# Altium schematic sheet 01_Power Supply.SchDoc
size 264 x 185 mm
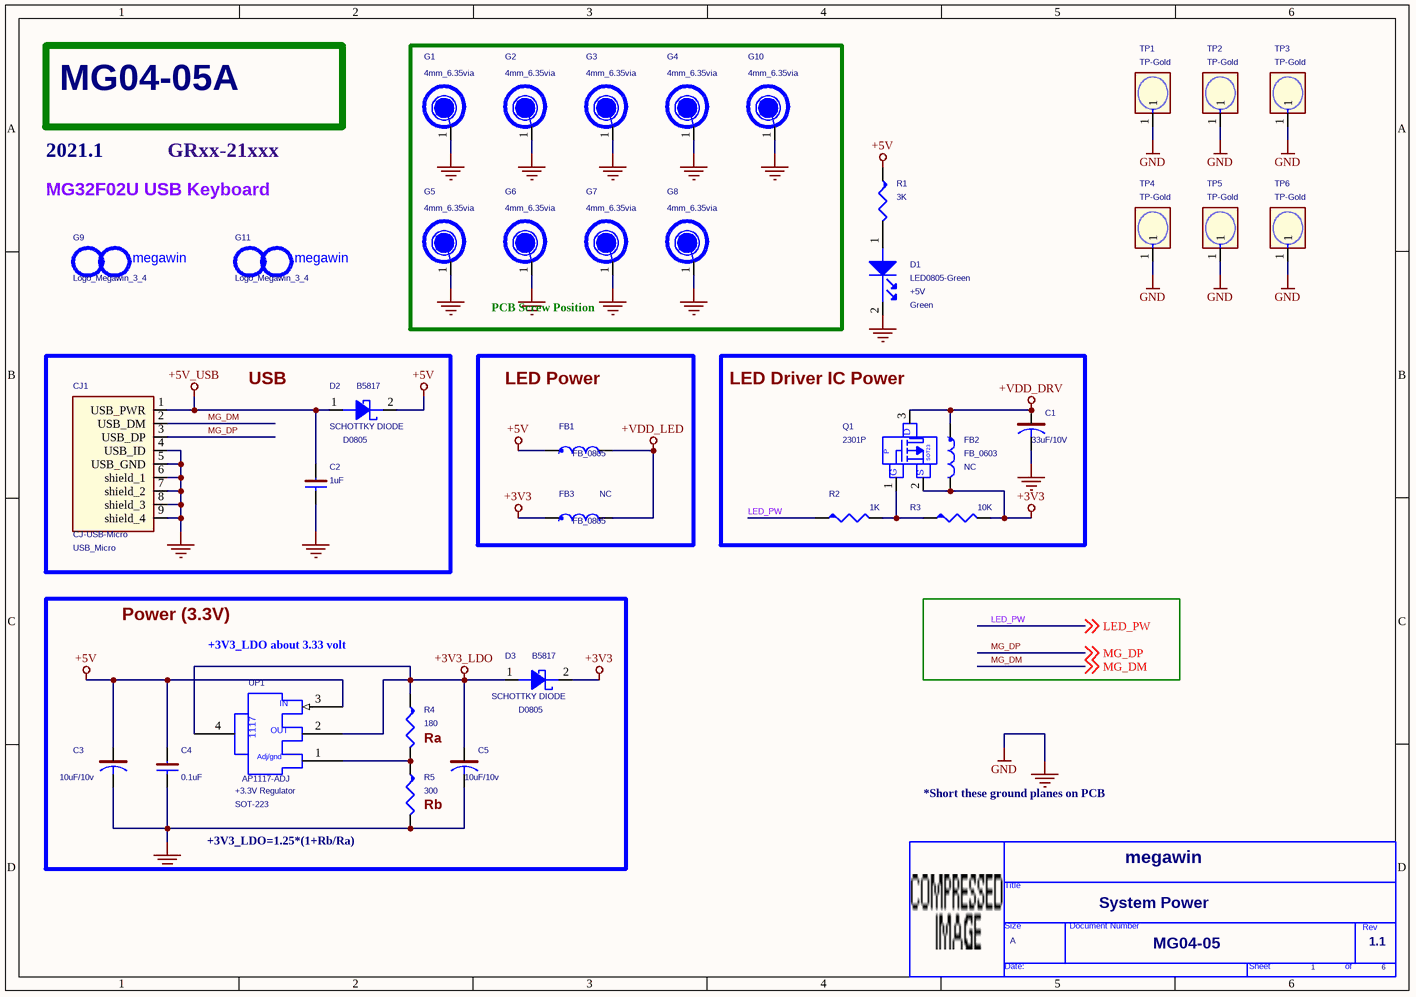
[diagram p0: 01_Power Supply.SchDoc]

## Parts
*  OrgName: megawin  Doc: MG04-05  RevCode: 1.1  Title: System Power  Page Size: A  Page Number: 1  Page Count: 6  (hidden comment: TitleBlock_MegaWin)  (graphical)
C1  33uF/10V  [C-0805]
C2  1uF  [C-0603]
C3  10uF/10v  [C-0805]
C4  0.1uF  [C-0603]
C5  10uF/10v  [C-0805]
CJ1  CJ-USB-Micro  Package: USB_Micro  [USB5A-MICRO-290X220P065]
D1  LED0805-Green  Function: +5V  Assembly: Green  [LED-0805]
D2  B5817  Package: D0805  Function: SCHOTTKY DIODE  [D-0805]
D3  B5817  Package: D0805  Function: SCHOTTKY DIODE  [D-0805]
FB1  FB_0805  [L-0603]
FB2  FB_0603  Assembly: NC  [L-0603]
FB3  FB_0805  Assembly: NC  [L-0603]
G1  4mm_6.35via  [SCREW1-H4-R6.35]
G2  4mm_6.35via  [SCREW1-H4-R6.35]
G3  4mm_6.35via  [SCREW1-H4-R6.35]
G4  4mm_6.35via  [SCREW1-H4-R6.35]
G5  4mm_6.35via  [SCREW1-H4-R6.35]
G6  4mm_6.35via  [SCREW1-H4-R6.35]
G7  4mm_6.35via  [SCREW1-H4-R6.35]
G8  4mm_6.35via  [SCREW1-H4-R6.35]
G9  Logo_Megawin_3_4  [MEGAWIN_4.9]  (no BOM)
G10  4mm_6.35via  [SCREW1-H4-R6.35]
G11  Logo_Megawin_3_4  [MEGAWIN_4.9]  (no BOM)
Q1  2301P  [SOT-23]
R1  3K  [R-0603]
R2  1K  [R-0603]
R3  10K  [R-0603]
R4  180  [R-0603]
R5  300  [R-0603]
TP1  TP-Gold  [SIP1-39]
TP2  TP-Gold  [SIP1-39]
TP3  TP-Gold  [SIP1-39]
TP4  TP-Gold  [SIP1-39]
TP5  TP-Gold  [SIP1-39]
TP6  TP-Gold  [SIP1-39]
UP1  AP1117-ADJ  Package: SOT-223  Function: +3.3V Regulator  [SOT223H\3P]

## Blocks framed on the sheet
PCB Screw Position: G1-G8 G10
USB: C2 CJ1 D2
LED Power: FB1 FB3
LED Driver IC Power: C1 FB2 Q1 R2 R3
Power (3.3V): C3-C5 D3 R4 R5 UP1

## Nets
+3V3: D3.2(CATHODE) FB2.2 FB3.1 Q1.2(S) R3.2
+3V3_LDO: C5.1 D3.1(ANODE) R4.1 UP1.2(OUT) UP1.4(VOUT)
+5V: C3.1 C4.1 D2.2(CATHODE) FB1.1 R1.1 UP1.3(IN)
+5V_USB: C2.1 CJ1.1(USB_PWR) D2.1(ANODE)
+VDD_DRV: C1.1 FB2.1 Q1.3(D)
+VDD_LED: FB1.2 FB3.2
GND: C1.2 C2.2 C3.2 C4.2 C5.2 CJ1.4(USB_ID) CJ1.5(USB_GND) CJ1.6(shield_1) CJ1.7(shield_2) CJ1.8(shield_3) CJ1.9(shield_4) D1.2(C) G1.1 G2.1 G3.1 G4.1 G5.1 G6.1 G7.1 G8.1 G10.1 R5.2 TP1.1 TP2.1 TP3.1 TP4.1 TP5.1 TP6.1
LED_PW: R2.1 ; off-sheet LED_PW
MG_DM: CJ1.2(USB_DM) ; off-sheet MG_DM
MG_DP: CJ1.3(USB_DP) ; off-sheet MG_DP
NetD1_1: D1.1(A) R1.2
NetQ1_1: Q1.1(G) R2.2 R3.1
NetR4_2: R4.2 R5.1 UP1.1(ADJ)

Not connected (* = marked no-connect by the designer): G9 1(.); G11 1(.)

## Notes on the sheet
- MG04-05A
- 2021.1
- MG32F02U USB Keyboard
- GRxx-21xxx
- +3V3_LDO about 3.33 volt
- (near R4) Ra
- (near R5) Rb
- (near *) *Short these ground planes on PCB
- +3V3_LDO=1.25*(1+Rb/Ra)

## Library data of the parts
C1 C3 C5 = CAP-POL
C2 = CAP-NP: 2ND PART FIELD: SMD_0805
C4 = CAP-NP
D1 = LED
D2 D3 = DIODE-SCHOTTKY-2
FB1-FB3 = FB2
G1-G8 G10 = ScrewPad-1P: MTG HOLE;ID2.5,OD6.6,NPTH,12 VIA; P/N: XXXXXXXXXXXX; {PCB Footprint}: SCREW9-H3.5-R8; Assembly: NC
G9 G11 = LOGO-Megawin_3_4: Assembly: NC
Q1 = MOS-P-SOT23
R1 = R: 2ND PART FIELD: SMD_0805
R2-R5 = R
TP1-TP6 = TPH-GND: Assembly: NC
UP1 = ICP-AP1117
